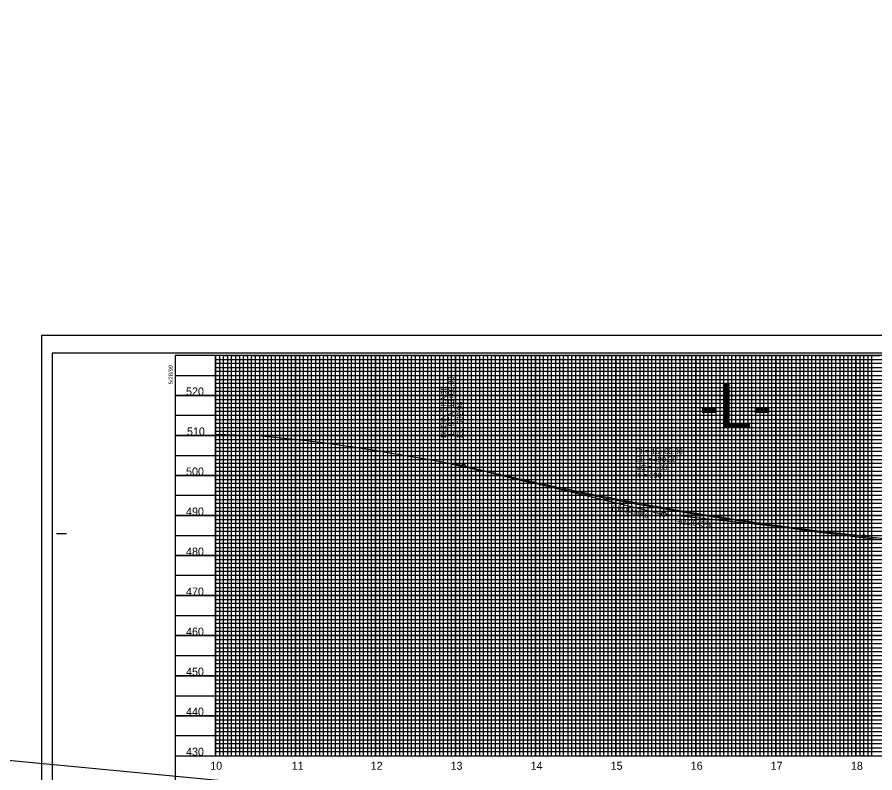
# Model space of a CAD drawing. Extents: x 571503 to 593215, y -77195 to -51828.
# Drawn here: x 581475 to 582546, y -53130 to -52186 of the extents above; entities that cross this region are included whole.
import ezdxf

# ---------------------------------------------------------------- set-up
doc = ezdxf.new("R2010")
doc.units = 0
for name, color, linetype in [('Default', 7, 'Continuous'), ('Exist Vertical Profile Ground Line', 7, 'Continuous'), ('Exist Vertical Profile Horizontal Axis Label Major', 7, 'Continuous'), ('Exist Vertical Profile Vertical Axis Label', 7, 'Continuous'), ('Prop PFL Text', 7, 'Continuous'), ('Prop Vertical Profile Curve Label', 7, 'Continuous'), ('Prop Vertical Profile Grade', 7, 'Continuous'), ('Prop Vertical Profile Grade Label', 7, 'Continuous'), ('Prop VPI Label', 7, 'Continuous'), ('Sheet Clip Boundary CELL', 7, 'Continuous'), ('Sheet DOT Grid CELL', 7, 'Continuous'), ('Sheet Plot Border Inside CELL', 7, 'Continuous'), ('Sheet Plot Border Outside CELL', 7, 'Continuous'), ('Sheet Profile CELL', 7, 'Continuous'), ('Sheet Profile Grid Major CELL', 7, 'Continuous'), ('Sheet Profile Grid Middle CELL', 7, 'Continuous'), ('Sheet Profile Grid Minor CELL', 7, 'Continuous')]:
    doc.layers.add(name, color=color, linetype=linetype)

msp = doc.modelspace()

# ---------------------------------------------------------------- linework, layer by layer
at = {"layer": 'Default'}
msp.add_line((581672.5, -53108.7), (581722.5, -53108.7), dxfattribs=at)
at = {"layer": 'Exist Vertical Profile Ground Line'}
for points in [[(581722.5, -52706.9), (581748.4, -52708), (581768.7, -52708.8), (581772.5, -52708.9)], [(581772.5, -52708.9), (581780.4, -52709.2), (581780.6, -52709.3), (581804.3, -52711.6), (581804.3, -52711.6), (581836.2, -52714.8), (581836.3, -52714.8), (581859.5, -52717.9), (581859.7, -52718), (581891.4, -52722.3), (581891.6, -52722.3), (581916, -52726.3), (581916.3, -52726.3), (581947.9, -52731.5), (581948.2, -52731.6), (581971.9, -52735.7), (581972.6, -52735.8), (582003.6, -52741.2), (582004.4, -52741.3), (582025.6, -52746), (582026.8, -52746.3), (582057.5, -52753.2), (582058.5, -52753.4), (582080.2, -52758.7), (582081.8, -52759.1), (582111.9, -52766.4), (582113.2, -52766.7), (582133.1, -52770.9), (582135.3, -52771.4), (582164.8, -52777.7), (582166.6, -52778.1), (582169.3, -52778.7), (582198.6, -52784.6), (582200.2, -52784.9), (582216.9, -52788.3), (582234.9, -52791.6), (582238.5, -52792.3), (582266.6, -52797.5), (582269.6, -52798.1), (582288.4, -52801.2), (582292.9, -52802), (582319.9, -52806.4), (582323.3, -52807), (582342.2, -52809.9), (582347.7, -52810.6), (582373.9, -52814.6), (582377.7, -52815.1), (582396.1, -52817.8), (582402.2, -52818.8), (582427.8, -52822.6), (582432.3, -52823.3), (582451, -52825.8), (582457.7, -52826.8), (582482.8, -52830.1), (582487.7, -52830.9), (582504.7, -52833), (582511.9, -52833.7), (582536.4, -52836.8), (582541.6, -52837.3), (582558.6, -52839.5)]]:
    msp.add_lwpolyline(points, dxfattribs=at)
at = {"layer": 'Prop PFL Text'}
msp.add_line((571620.7, -52186.3), (592499.5, -54154.9), dxfattribs=at)
at = {"layer": 'Prop Vertical Profile Curve Label'}
for centre in [(582032.5, -52746.5), (582532.5, -52834.6)]:
    msp.add_circle(centre, 2.25, dxfattribs=at)
at = {"layer": 'Prop Vertical Profile Grade'}
for p, q in [((582022.5, -52744.1), (582032.5, -52746.5)), ((582532.5, -52834.6), (582684.5, -52851.4))]:
    msp.add_line(p, q, dxfattribs=at)
msp.add_spline([(582032.5, -52746.5), (582042.5, -52749), (582052.5, -52751.3), (582062.5, -52753.7), (582072.5, -52756), (582082.5, -52758.3), (582092.5, -52760.6), (582102.5, -52762.8), (582112.5, -52765.1), (582122.5, -52767.3), (582132.5, -52769.4), (582142.5, -52771.6), (582152.5, -52773.7), (582162.5, -52775.8), (582172.5, -52777.8), (582182.5, -52779.9), (582192.5, -52781.9), (582202.5, -52783.9), (582212.5, -52785.8), (582222.5, -52787.8), (582232.5, -52789.7), (582242.5, -52791.6), (582252.5, -52793.4), (582262.5, -52795.2), (582272.5, -52797), (582282.5, -52798.8), (582292.5, -52800.6), (582302.5, -52802.3), (582312.5, -52804), (582322.5, -52805.6), (582332.5, -52807.3), (582342.5, -52808.9), (582352.5, -52810.5), (582362.5, -52812.1), (582372.5, -52813.6), (582382.5, -52815.1), (582392.5, -52816.6), (582402.5, -52818), (582412.5, -52819.5), (582422.5, -52820.9), (582432.5, -52822.3), (582442.5, -52823.6), (582452.5, -52824.9), (582462.5, -52826.2), (582472.5, -52827.5), (582482.5, -52828.8), (582492.5, -52830), (582502.5, -52831.2), (582512.5, -52832.3), (582522.5, -52833.5), (582532.5, -52834.6)], degree=3, dxfattribs=at)
at = {"layer": 'Prop VPI Label'}
for p, q in [((582022.5, -52744.1), (582022.5, -52620)), ((582032.5, -52746.5), (582279.8, -52806.4)), ((582532.5, -52834.6), (582285.2, -52807.4))]:
    msp.add_line(p, q, dxfattribs=at)
msp.add_circle((582282.5, -52807), 2.75, dxfattribs=at)
at = {"layer": 'Sheet Clip Boundary CELL'}
msp.add_lwpolyline([(581722.5, -52608.7), (581722.5, -53108.7), (583122.5, -53108.7), (583122.5, -52746.2), (582972.5, -52746.2), (582972.5, -52608.7)], close=True, dxfattribs=at)
at = {"layer": 'Sheet DOT Grid CELL'}
for p, q in [((581722.5, -53108.7), (581722.5, -52608.7)), ((581722.5, -53108.7), (581722.5, -52608.7)), ((581772.5, -53108.7), (581772.5, -52608.7)), ((581772.5, -53108.7), (581772.5, -52608.7)), ((581822.5, -53108.7), (581822.5, -52608.7)), ((581822.5, -53108.7), (581822.5, -52608.7)), ((581872.5, -53108.7), (581872.5, -52608.7)), ((581872.5, -53108.7), (581872.5, -52608.7)), ((581922.5, -53108.7), (581922.5, -52608.7)), ((581922.5, -53108.7), (581922.5, -52608.7)), ((581972.5, -53108.7), (581972.5, -52608.7)), ((581972.5, -53108.7), (581972.5, -52608.7)), ((582022.5, -53108.7), (582022.5, -52608.7)), ((582022.5, -53108.7), (582022.5, -52608.7)), ((582072.5, -53108.7), (582072.5, -52608.7)), ((582072.5, -53108.7), (582072.5, -52608.7)), ((582122.5, -53108.7), (582122.5, -52608.7)), ((582122.5, -53108.7), (582122.5, -52608.7)), ((582172.5, -53108.7), (582172.5, -52608.7)), ((582172.5, -53108.7), (582172.5, -52608.7)), ((582222.5, -53108.7), (582222.5, -52608.7)), ((582222.5, -53108.7), (582222.5, -52608.7)), ((582272.5, -53108.7), (582272.5, -52608.7)), ((582272.5, -53108.7), (582272.5, -52608.7)), ((582322.5, -53108.7), (582322.5, -52608.7)), ((582322.5, -53108.7), (582322.5, -52608.7)), ((582372.5, -53108.7), (582372.5, -52608.7)), ((582372.5, -53108.7), (582372.5, -52608.7)), ((582422.5, -53108.7), (582422.5, -52608.7)), ((582422.5, -53108.7), (582422.5, -52608.7)), ((582472.5, -53108.7), (582472.5, -52608.7)), ((582472.5, -53108.7), (582472.5, -52608.7)), ((582522.5, -53108.7), (582522.5, -52608.7)), ((582522.5, -53108.7), (582522.5, -52608.7)), ((581672.5, -52658.7), (582972.5, -52658.7)), ((582972.5, -52658.7), (581672.5, -52658.7)), ((581672.5, -52708.7), (582972.5, -52708.7)), ((582972.5, -52708.7), (581672.5, -52708.7)), ((581672.5, -52758.7), (583172.5, -52758.7)), ((583172.5, -52758.7), (581672.5, -52758.7)), ((581672.5, -52808.7), (583172.5, -52808.7)), ((583172.5, -52808.7), (581672.5, -52808.7)), ((581672.5, -52858.7), (583172.5, -52858.7)), ((583172.5, -52858.7), (581672.5, -52858.7)), ((581672.5, -52908.7), (583172.5, -52908.7)), ((583172.5, -52908.7), (581672.5, -52908.7)), ((581672.5, -52958.7), (583172.5, -52958.7)), ((583172.5, -52958.7), (581672.5, -52958.7)), ((581672.5, -53008.7), (583172.5, -53008.7)), ((583172.5, -53008.7), (581672.5, -53008.7)), ((581672.5, -53058.7), (583172.5, -53058.7)), ((583172.5, -53058.7), (581672.5, -53058.7))]:
    msp.add_line(p, q, dxfattribs=at)
at = {"layer": 'Sheet Plot Border Inside CELL'}
msp.add_lwpolyline([(581518.5, -53661.2), (583185, -53661.2), (583185, -52606.1), (581518.5, -52606.1)], close=True, dxfattribs=at)
at = {"layer": 'Sheet Plot Border Outside CELL'}
msp.add_lwpolyline([(581505.5, -53683.7), (583189.5, -53683.7), (583189.5, -52583.7), (581505.5, -52583.7)], close=True, dxfattribs=at)
at = {"layer": 'Sheet Profile CELL'}
for p, q in [((583189.5, -52583.7), (581505.5, -52583.7)), ((581505.5, -52583.7), (581505.5, -53683.7)), ((581524, -52831.2), (581536.5, -52831.2)), ((581672.5, -53108.7), (583172.5, -53108.7))]:
    msp.add_line(p, q, dxfattribs=at)
msp.add_lwpolyline([(583172.5, -52608.7), (581672.5, -52608.7), (581672.5, -53658.7), (583172.5, -53658.7)], close=True, dxfattribs=at)
at = {"layer": 'Sheet Profile Grid Major CELL'}
for points in [[(581722.5, -52608.7), (581722.5, -53108.7), (581772.5, -53108.7), (581772.5, -52608.7), (581822.5, -52608.7), (581822.5, -53108.7), (581872.5, -53108.7), (581872.5, -52608.7), (581922.5, -52608.7), (581922.5, -53108.7), (581972.5, -53108.7), (581972.5, -52608.7), (582022.5, -52608.7), (582022.5, -53108.7), (582072.5, -53108.7), (582072.5, -52608.7), (582122.5, -52608.7), (582122.5, -53108.7), (582172.5, -53108.7), (582172.5, -52608.7), (582222.5, -52608.7), (582222.5, -53108.7), (582272.5, -53108.7), (582272.5, -52608.7), (582322.5, -52608.7), (582322.5, -53108.7), (582372.5, -53108.7), (582372.5, -52608.7), (582422.5, -52608.7), (582422.5, -53108.7), (582472.5, -53108.7), (582472.5, -52608.7), (582522.5, -52608.7), (582522.5, -53108.7), (582572.5, -53108.7)], [(581672.5, -52658.7), (582972.5, -52658.7)], [(582972.5, -52708.7), (581672.5, -52708.7), (581672.5, -52758.7), (583172.5, -52758.7)], [(583172.5, -52808.7), (581672.5, -52808.7), (581672.5, -52858.7), (583172.5, -52858.7)], [(583172.5, -52908.7), (581672.5, -52908.7), (581672.5, -52958.7), (583172.5, -52958.7)], [(583172.5, -53008.7), (581672.5, -53008.7), (581672.5, -53008.7), (581672.5, -53058.7), (583172.5, -53058.7)]]:
    msp.add_lwpolyline(points, dxfattribs=at)
at = {"layer": 'Sheet Profile Grid Middle CELL'}
msp.add_line((581672.5, -52633.7), (582972.5, -52633.7), dxfattribs=at)
for points in [[(581747.5, -52608.7), (581747.5, -53108.7), (581797.5, -53108.7), (581797.5, -52608.7), (581847.5, -52608.7), (581847.5, -53108.7), (581897.5, -53108.7), (581897.5, -52608.7), (581947.5, -52608.7), (581947.5, -53108.7), (581997.5, -53108.7), (581997.5, -52608.7), (582047.5, -52608.7), (582047.5, -53108.7), (582097.5, -53108.7), (582097.5, -52608.7), (582147.5, -52608.7), (582147.5, -53108.7), (582197.5, -53108.7), (582197.5, -52608.7), (582247.5, -52608.7), (582247.5, -53108.7), (582297.5, -53108.7), (582297.5, -53108.7), (582297.5, -52608.7), (582347.5, -52608.7), (582347.5, -53108.7), (582397.5, -53108.7), (582397.5, -52608.7), (582447.5, -52608.7), (582447.5, -53108.7), (582497.5, -53108.7), (582497.5, -52608.7), (582547.5, -52608.7)], [(582972.5, -52683.7), (581672.5, -52683.7), (581672.5, -52733.7), (582972.5, -52733.7)], [(583172.5, -52783.7), (581672.5, -52783.7), (581672.5, -52833.7), (582997.5, -52833.7)], [(583172.5, -52883.7), (581672.5, -52883.7), (581672.5, -52933.7), (583172.5, -52933.7)], [(583172.5, -52983.7), (581672.5, -52983.7), (581672.5, -53033.7), (583172.5, -53033.7)], [(583172.5, -53083.7), (581672.5, -53083.7)]]:
    msp.add_lwpolyline(points, dxfattribs=at)
at = {"layer": 'Sheet Profile Grid Minor CELL'}
for p, q in [((581722.5, -52613.7), (582972.5, -52613.7)), ((581722.5, -52618.7), (581722.5, -52618.7)), ((582972.5, -52618.7), (581722.5, -52619)), ((581722.5, -52623.7), (582972.5, -52623.7)), ((582972.5, -52743.7), (581722.5, -52743.7)), ((583122.5, -52748.7), (581722.5, -52748.7)), ((583122.5, -52753.7), (581722.5, -52753.7)), ((581722.5, -52763.7), (583122.5, -52763.7)), ((583122.5, -52768.7), (581722.5, -52768.7)), ((581722.5, -52773.7), (583122.5, -52773.7)), ((583122.5, -52793.7), (581722.5, -52793.7)), ((581722.5, -52798.7), (583122.5, -52798.7)), ((583122.5, -52818.7), (581722.5, -52818.7)), ((581722.5, -52823.7), (583122.5, -52823.7)), ((583122.5, -52843.7), (581722.5, -52843.7)), ((581722.5, -52848.7), (583122.5, -52848.7)), ((583122.5, -52853.7), (581722.5, -52853.7)), ((581722.5, -52863.7), (583122.5, -52863.7)), ((583122.5, -52868.7), (581722.5, -52868.7)), ((581722.5, -52873.7), (583122.5, -52873.7)), ((583122.5, -52878.7), (581722.5, -52878.7)), ((581722.5, -52888.7), (583122.5, -52888.7)), ((583122.5, -52893.7), (581722.5, -52893.7)), ((581722.5, -52898.7), (583122.5, -52898.7)), ((583122.5, -52903.7), (581722.5, -52903.7)), ((581722.5, -52913.7), (583122.5, -52913.7)), ((583122.5, -52918.7), (581722.5, -52918.7)), ((581722.5, -52923.7), (583122.5, -52923.7)), ((583122.5, -52928.7), (581722.5, -52928.7)), ((581722.5, -52938.7), (583122.5, -52938.7)), ((583122.5, -52943.7), (581722.5, -52943.7)), ((581722.5, -52948.7), (583122.5, -52948.7)), ((583122.5, -52953.7), (581722.5, -52953.7)), ((581722.5, -52963.7), (583122.5, -52963.7)), ((583122.5, -52968.7), (581722.5, -52968.7)), ((581722.5, -52973.7), (583122.5, -52973.7)), ((583122.5, -52978.7), (581722.5, -52978.7)), ((581722.5, -52988.7), (583122.5, -52988.7)), ((583122.5, -52993.7), (581722.5, -52993.7)), ((583122.5, -52998.7), (581722.5, -52998.7)), ((583122.5, -53003.7), (581722.5, -53003.7)), ((581722.5, -53013.7), (583122.5, -53013.7)), ((583122.5, -53018.7), (581722.5, -53018.7)), ((581722.5, -53023.7), (583122.5, -53023.7)), ((583122.5, -53028.7), (581722.5, -53028.7)), ((581722.5, -53038.7), (583122.5, -53038.7)), ((583122.5, -53043.7), (581722.5, -53043.7)), ((581722.5, -53048.7), (583122.5, -53048.7)), ((583122.5, -53053.7), (581722.5, -53053.7)), ((581722.5, -53063.7), (583122.5, -53063.7)), ((583122.5, -53068.7), (581722.5, -53068.7)), ((581722.5, -53073.7), (583122.5, -53073.7)), ((583122.5, -53078.7), (581722.5, -53078.7)), ((581722.5, -53088.7), (583122.5, -53088.7)), ((583122.5, -53093.7), (581722.5, -53093.7)), ((581722.5, -53098.7), (583122.5, -53098.7))]:
    msp.add_line(p, q, dxfattribs=at)
for points in [[(581727.5, -52608.7), (581727.5, -53108.7), (581732.5, -53108.7), (581732.5, -52608.7), (581737.5, -52608.7), (581737.5, -53108.7), (581742.5, -53108.7), (581742.5, -52608.7), (581752.5, -52608.7), (581752.5, -53108.7), (581757.5, -53108.7), (581757.5, -52608.7), (581762.5, -52608.7), (581762.5, -53108.7), (581767.5, -53108.7), (581777.5, -53108.7), (581782.5, -53108.7), (581782.5, -52608.7), (581787.5, -52608.7), (581787.5, -53108.7), (581792.5, -53108.7), (581792.5, -52608.7), (581802.5, -52608.7), (581802.5, -53108.7), (581807.5, -53108.7), (581807.5, -52608.7), (581812.5, -52608.7), (581812.5, -53108.7), (581817.5, -53108.7), (581817.5, -52608.7), (581827.5, -52608.7), (581827.5, -53108.7), (581832.5, -53108.7), (581832.5, -52608.7), (581837.5, -52608.7), (581837.5, -53108.7), (581842.5, -53108.7), (581842.5, -52608.7), (581852.5, -52608.7), (581852.5, -53108.7), (581857.5, -53108.7), (581857.5, -52608.7), (581862.5, -52608.7), (581862.5, -53108.7), (581867.5, -53108.7), (581867.5, -52608.7), (581877.5, -52608.7), (581877.5, -53108.7), (581882.5, -53108.7), (581882.5, -52608.7), (581887.5, -52608.7), (581887.5, -53108.7), (581892.5, -53108.7), (581892.5, -52608.7), (581902.5, -52608.7), (581902.5, -53108.7), (581907.5, -53108.7), (581907.5, -52608.7), (581912.5, -52608.7), (581912.5, -53108.7), (581917.5, -53108.7), (581917.5, -52608.7), (581927.5, -52608.7), (581927.5, -53108.7), (581932.5, -53108.7), (581932.5, -52608.7), (581937.5, -52608.7), (581937.5, -53108.7)], [(581767.5, -53108.7), (581767.5, -52608.7), (581777.5, -52608.7), (581777.5, -53108.7)], [(581937.5, -53108.7), (581942.5, -53108.7), (581942.5, -52608.7), (581952.5, -52608.7), (581952.5, -53108.7), (581957.5, -53108.7), (581957.5, -52608.7), (581962.5, -52608.7), (581962.5, -53108.7), (581967.5, -53108.7), (581967.5, -52608.7), (581977.5, -52608.7), (581977.5, -53108.7), (581982.5, -53108.7), (581982.5, -52608.7), (581987.5, -52608.7), (581987.5, -53108.7), (581992.5, -53108.7), (581992.5, -52608.7), (582002.5, -52608.7), (582002.5, -53108.7), (582007.5, -53108.7), (582007.5, -52608.7), (582012.5, -52608.7), (582012.5, -53108.7), (582017.5, -53108.7), (582017.5, -52608.7), (582027.5, -52608.7), (582027.5, -53108.7), (582032.5, -53108.7), (582032.5, -52608.7), (582037.5, -52608.7), (582037.5, -53108.7), (582042.5, -53108.7), (582042.5, -52608.7), (582052.5, -52608.7), (582052.5, -53108.7), (582057.5, -53108.7), (582057.5, -52608.7), (582062.5, -52608.7), (582062.5, -53108.7), (582067.5, -53108.7), (582067.5, -52608.7), (582077.5, -52608.7), (582077.5, -53108.7), (582082.5, -53108.7), (582082.5, -52608.7), (582087.5, -52608.7), (582087.5, -53108.7), (582092.5, -53108.7), (582092.5, -52608.7), (582102.5, -52608.7), (582102.5, -53108.7), (582107.5, -53108.7), (582107.5, -52608.7), (582112.5, -52608.7), (582112.5, -53108.7), (582117.5, -53108.7), (582117.5, -52608.7), (582127.5, -52608.7), (582127.5, -53108.7), (582132.5, -53108.7), (582132.5, -52608.7), (582137.5, -52608.7), (582137.5, -53108.7), (582142.5, -53108.7), (582142.5, -52608.7), (582152.5, -52608.7), (582152.5, -53108.7), (582157.5, -53108.7), (582157.5, -52608.7), (582162.5, -52608.7), (582162.5, -53108.7), (582167.5, -53108.7), (582167.5, -52608.7), (582177.5, -52608.7), (582177.5, -53108.7), (582182.5, -53108.7), (582182.5, -52608.7), (582187.5, -52608.7), (582187.5, -53108.7), (582192.5, -53108.7), (582192.5, -52608.7), (582202.5, -52608.7), (582202.5, -53108.7), (582207.5, -53108.7), (582207.5, -52608.7), (582212.5, -52608.7), (582212.5, -53108.7), (582217.5, -53108.7), (582217.5, -52608.7), (582227.5, -52608.7), (582227.5, -53108.7), (582232.5, -53108.7), (582232.5, -52608.7), (582237.5, -52608.7), (582237.5, -53108.7), (582242.5, -53108.7), (582242.5, -52608.7), (582252.5, -52608.7)], [(582252.5, -52608.7), (582252.5, -53108.7), (582257.5, -53108.7), (582257.5, -52608.7), (582262.5, -52608.7), (582262.5, -53108.7), (582267.5, -53108.7), (582267.5, -52608.7), (582277.5, -52608.7), (582277.5, -53108.7), (582282.5, -53108.7), (582282.5, -52608.7), (582287.5, -52608.7), (582287.5, -53108.7), (582292.5, -53108.7), (582292.5, -52608.7), (582302.5, -52608.7), (582302.5, -53108.7), (582307.5, -53108.7), (582307.5, -52608.7), (582312.5, -52608.7), (582312.5, -53108.7), (582317.5, -53108.7), (582317.5, -52608.7), (582327.5, -52608.7), (582327.5, -53108.7), (582332.5, -53108.7), (582332.5, -52608.7), (582337.5, -52608.7), (582337.5, -53108.7), (582342.5, -53108.7), (582342.5, -52608.7), (582352.5, -52608.7), (582352.5, -53108.7), (582357.5, -53108.7), (582357.5, -52608.7), (582362.5, -52608.7), (582362.5, -53108.7), (582367.5, -53108.7), (582367.5, -52608.7), (582377.5, -52608.7), (582377.5, -53108.7), (582377.5, -53108.7), (582382.5, -53108.7), (582382.5, -52608.7), (582387.5, -52608.7), (582387.5, -53108.7), (582392.5, -53108.7), (582392.5, -52608.7), (582402.5, -52608.7), (582402.5, -53108.7), (582407.5, -53108.7), (582407.5, -52608.7), (582412.5, -52608.7), (582412.5, -53108.7), (582417.5, -53108.7), (582417.5, -52608.7), (582427.5, -52608.7), (582427.5, -53108.7), (582432.5, -53108.7), (582432.5, -52608.7), (582437.5, -52608.7), (582437.5, -53108.7), (582442.5, -53108.7), (582442.5, -52608.7), (582452.5, -52608.7), (582452.5, -53108.7), (582457.5, -53108.7), (582457.5, -52608.7), (582462.5, -52608.7), (582462.5, -53108.7), (582467.5, -53108.7), (582467.5, -52608.7), (582477.5, -52608.7), (582477.5, -53108.7), (582482.5, -53108.7), (582482.5, -52608.7), (582487.5, -52608.7), (582487.5, -53108.7), (582492.5, -53108.7), (582492.5, -52608.7), (582502.5, -52608.7), (582502.5, -53108.7), (582507.5, -53108.7), (582507.5, -52608.7), (582512.5, -52608.7), (582512.5, -53108.7), (582517.5, -53108.7), (582517.5, -52608.7), (582527.5, -52608.7), (582527.5, -53108.7), (582532.2, -53108.1), (582532.5, -53108.7), (582532.5, -52608.7), (582537.5, -52608.7), (582537.5, -53108.7), (582542.5, -53108.7), (582542.5, -52608.7), (582552.5, -52608.7)], [(582972.5, -52628.7), (581722.5, -52628.7), (581722.5, -52638.7), (582972.5, -52638.7)], [(582972.5, -52643.7), (581722.5, -52643.7), (581722.5, -52648.7), (582972.5, -52648.7)], [(582972.5, -52653.7), (581722.5, -52653.7), (581722.5, -52663.7), (582972.5, -52663.7)], [(582972.5, -52668.7), (581722.5, -52668.7), (581722.5, -52673.7), (582972.5, -52673.7)], [(582972.5, -52678.7), (581722.5, -52678.7), (581722.5, -52688.7), (582972.5, -52688.7)], [(582972.5, -52693.7), (581722.5, -52693.7), (581722.5, -52698.7), (582972.5, -52698.7)], [(582972.5, -52703.7), (581722.5, -52703.7), (581722.5, -52713.7), (582972.5, -52713.7)], [(582972.5, -52718.8), (581722.6, -52718.8), (581722.6, -52723.7), (582972.5, -52723.7)], [(582972.5, -52728.7), (581722.5, -52728.7), (581722.5, -52738.7), (582972.5, -52738.7)], [(583122.5, -52778.7), (581722.5, -52778.7), (581722.5, -52788.7), (583122.5, -52788.7)], [(583122.5, -52803.7), (581722.5, -52803.7), (581722.5, -52813.7), (583122.5, -52813.7)], [(583122.5, -52828.7), (581722.5, -52828.7), (581722.5, -52838.7), (583122.5, -52838.7)], [(583122.5, -53103.7), (581722.5, -53103.7)]]:
    msp.add_lwpolyline(points, dxfattribs=at)

# ---------------------------------------------------------------- texts
at = {"layer": 'Default'}
msp.add_text('-L-', height=55.36, dxfattribs=at).set_placement((582327, -52699))
at = {"layer": 'Exist Vertical Profile Horizontal Axis Label Major'}
for s, p in [('10', (581716.1, -53126.2)), ('11', (581817.9, -53126.2)), ('12', (581916.5, -53126.2)), ('13', (582016.3, -53126.2)), ('14', (582116.2, -53126.2)), ('15', (582216.2, -53126.2)), ('16', (582316.2, -53126.2)), ('17', (582416, -53126.2)), ('18', (582516.2, -53126.2))]:
    msp.add_text(s, height=10, dxfattribs=at).set_placement(p)
at = {"layer": 'Exist Vertical Profile Vertical Axis Label'}
for s, p in [('520', (581685.9, -52658.7)), ('520', (581685.9, -52658.7)), ('510', (581687.1, -52708.7)), ('510', (581687.1, -52708.7)), ('500', (581685.9, -52758.7)), ('500', (581685.9, -52758.7)), ('490', (581685.9, -52808.7)), ('490', (581685.9, -52808.7)), ('480', (581685.9, -52858.7)), ('480', (581685.9, -52858.7)), ('470', (581685.9, -52908.7)), ('470', (581685.9, -52908.7)), ('460', (581685.9, -52958.7)), ('460', (581685.9, -52958.7)), ('450', (581685.9, -53008.7)), ('450', (581685.9, -53008.7)), ('440', (581685.9, -53058.7)), ('440', (581685.9, -53058.7)), ('430', (581685.9, -53108.7)), ('430', (581685.9, -53108.7))]:
    msp.add_text(s, height=10, dxfattribs=at).set_placement(p)
at = {"layer": 'Prop Vertical Profile Curve Label'}
for s, p in [("VC = 500'", (582247.5, -52752)), ('K = 190', (582247.5, -52761.9))]:
    msp.add_text(s, height=7, dxfattribs=at).set_placement(p)
at = {"layer": 'Prop Vertical Profile Grade Label'}
for s, rotation, p in [('(-)4.8400%', 346.396, (582217.2, -52801.5)), ('(-)2.2045%', 353.7099, (582295.9, -52818.6))]:
    msp.add_text(s, height=7, rotation=rotation, dxfattribs=at).set_placement(p)
at = {"layer": 'Prop VPI Label'}
for s, p in [('-L- STA. 13+00.00', (582020.4, -52711.6)), ('BEGIN GRADE', (582011.1, -52711.6)), ('EL. 502.96', (582031.2, -52711.7))]:
    msp.add_text(s, height=7, rotation=90, dxfattribs=at).set_placement(p)
for s, p in [('PI = 15+60.00', (582247.5, -52732)), ("EL = 490.38'", (582247.5, -52742))]:
    msp.add_text(s, height=7, dxfattribs=at).set_placement(p)
at = {"layer": 'Sheet Profile CELL'}
msp.add_text('5/28/99', height=5.25, rotation=90, dxfattribs=at).set_placement((581669.3, -52644.8))

doc.saveas('drawing.dxf')
